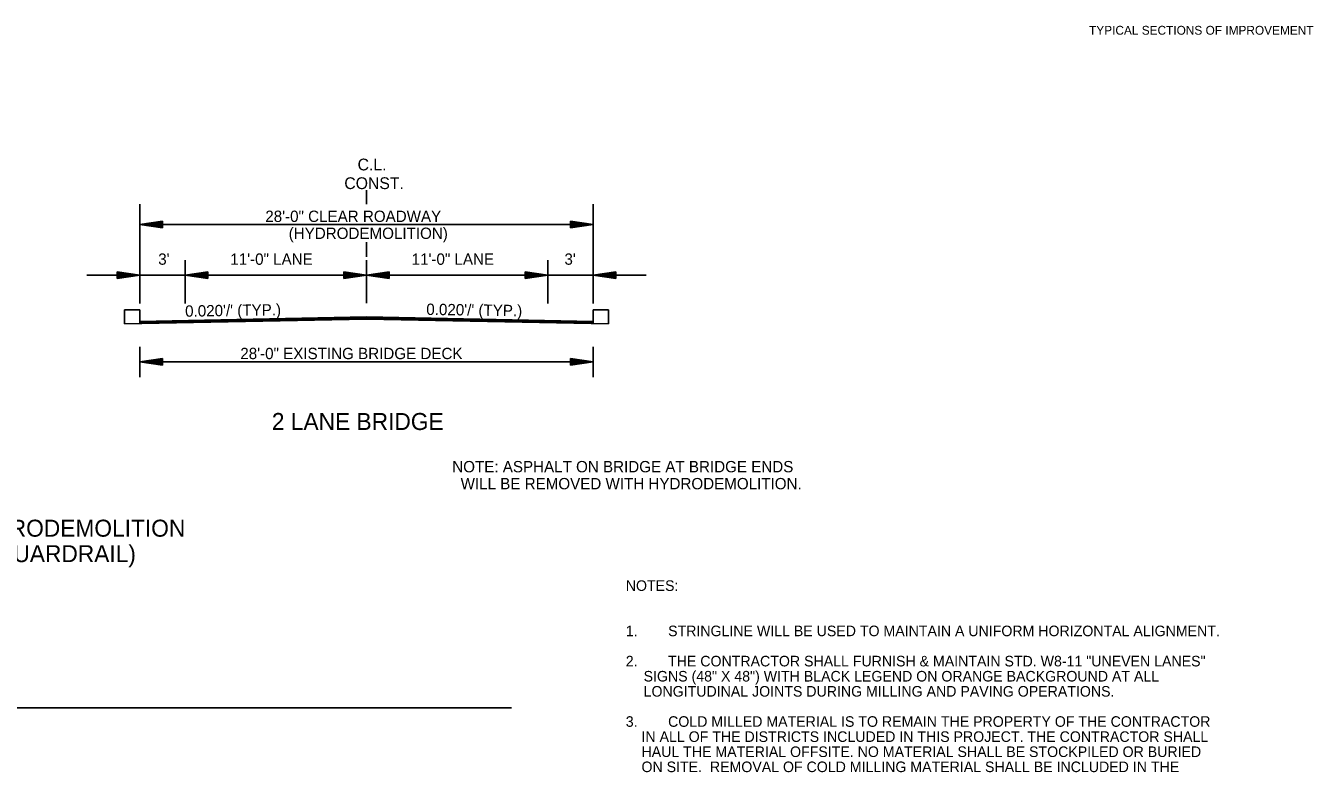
# Model space of a CAD drawing. Extents: x 544259 to 1930787, y -1961343 to 596640.
# Drawn here: x 544903 to 545755, y -1960851 to -1960356 of the extents above; entities that cross this region are included whole.
import ezdxf

# ---------------------------------------------------------------- set-up
doc = ezdxf.new("R2010")
doc.units = 0
for name, color, linetype in [('R_Border', 7, 'Continuous'), ('R_Border Notes', 7, 'Continuous'), ('R_Border Prem', 7, 'Continuous'), ('R_Draft', 7, 'Continuous')]:
    doc.layers.add(name, color=color, linetype=linetype)

msp = doc.modelspace()

# ---------------------------------------------------------------- linework, layer by layer
at = {"layer": 'R_Border'}
for p, q in [((544968.48, -1960544.64), (544968.47, -1960553.85)), ((544978.65, -1960544.64), (544968.48, -1960544.64)), ((544978.65, -1960553.38), (544978.65, -1960544.64)), ((545278.65, -1960553.38), (545278.65, -1960544.64)), ((545278.65, -1960544.64), (545288.82, -1960544.64)), ((545288.82, -1960544.64), (545288.83, -1960553.85)), ((544303.14, -1960808.08), (545224.71, -1960808.08))]:
    msp.add_line(p, q, dxfattribs=at)
at = {"layer": 'R_Draft'}
for p, q in [((545128.65, -1960474.62), (545128.65, -1960465.31)), ((544978.65, -1960540.4), (544978.65, -1960474.66)), ((545278.65, -1960540.4), (545278.65, -1960474.66)), ((544993.65, -1960485.78), (544978.65, -1960488.03)), ((544993.65, -1960490.28), (544978.65, -1960488.03)), ((544993.65, -1960486.16), (544981.15, -1960488.03)), ((544993.65, -1960489.91), (544981.15, -1960488.03)), ((544993.65, -1960486.54), (544983.73, -1960488.03)), ((544993.65, -1960489.53), (544983.73, -1960488.03)), ((544993.65, -1960486.92), (544986.23, -1960488.03)), ((544993.65, -1960489.15), (544986.23, -1960488.03)), ((544993.65, -1960487.3), (544988.77, -1960488.03)), ((544993.65, -1960488.76), (544988.77, -1960488.03)), ((544990.65, -1960488.03), (545266.65, -1960488.03)), ((544993.65, -1960487.68), (544991.28, -1960488.03)), ((544993.65, -1960488.39), (544991.28, -1960488.03)), ((544993.65, -1960490.28), (544993.65, -1960485.78)), ((545263.65, -1960485.78), (545278.65, -1960488.03)), ((545263.65, -1960485.78), (545263.65, -1960490.28)), ((545263.65, -1960486.16), (545276.14, -1960488.03)), ((545263.65, -1960486.54), (545273.56, -1960488.03)), ((545263.65, -1960486.92), (545271.07, -1960488.03)), ((545263.65, -1960487.31), (545268.52, -1960488.03)), ((545263.65, -1960487.68), (545266.02, -1960488.03)), ((545263.65, -1960490.28), (545278.65, -1960488.03)), ((545263.65, -1960488.77), (545268.52, -1960488.03)), ((545263.65, -1960489.53), (545273.56, -1960488.03)), ((545263.65, -1960489.91), (545276.14, -1960488.03)), ((545263.65, -1960489.15), (545271.07, -1960488.03)), ((545263.65, -1960488.39), (545266.02, -1960488.03)), ((545128.65, -1960509.55), (545128.65, -1960499.68)), ((545008.65, -1960540.4), (545008.65, -1960511.68)), ((545128.65, -1960540.23), (545128.65, -1960511.68)), ((545248.65, -1960540.4), (545248.65, -1960511.68)), ((545008.65, -1960521.57), (544943.65, -1960521.57)), ((544963.65, -1960519.32), (544978.65, -1960521.57)), ((544963.65, -1960519.32), (544963.65, -1960523.82)), ((544963.65, -1960519.7), (544976.14, -1960521.57)), ((544963.65, -1960520.08), (544973.56, -1960521.57)), ((544963.65, -1960520.45), (544971.07, -1960521.57)), ((544963.65, -1960520.84), (544968.52, -1960521.57)), ((544963.65, -1960521.22), (544966.02, -1960521.57)), ((544963.65, -1960523.82), (544978.65, -1960521.57)), ((544963.65, -1960522.31), (544968.52, -1960521.57)), ((544963.65, -1960523.06), (544973.56, -1960521.57)), ((544963.65, -1960523.45), (544976.14, -1960521.57)), ((544963.65, -1960522.69), (544971.07, -1960521.57)), ((544963.65, -1960521.92), (544966.02, -1960521.57)), ((545023.65, -1960519.32), (545008.65, -1960521.57)), ((545023.65, -1960523.82), (545008.65, -1960521.57)), ((545008.65, -1960521.57), (545128.65, -1960521.57)), ((545023.65, -1960519.7), (545011.15, -1960521.57)), ((545023.65, -1960523.45), (545011.15, -1960521.57)), ((545023.65, -1960520.08), (545013.73, -1960521.57)), ((545023.65, -1960523.06), (545013.73, -1960521.57)), ((545023.65, -1960520.45), (545016.23, -1960521.57)), ((545023.65, -1960522.69), (545016.23, -1960521.57)), ((545023.65, -1960520.84), (545018.77, -1960521.57)), ((545023.65, -1960522.3), (545018.77, -1960521.57)), ((545023.65, -1960521.22), (545021.28, -1960521.57)), ((545023.65, -1960521.92), (545021.28, -1960521.57)), ((545023.65, -1960523.82), (545023.65, -1960519.32)), ((545113.65, -1960519.32), (545128.65, -1960521.57)), ((545113.65, -1960519.32), (545113.65, -1960523.82)), ((545113.65, -1960519.7), (545126.14, -1960521.57)), ((545113.65, -1960520.08), (545123.56, -1960521.57)), ((545113.65, -1960520.45), (545121.07, -1960521.57)), ((545113.65, -1960520.84), (545118.52, -1960521.57)), ((545113.65, -1960521.22), (545116.02, -1960521.57)), ((545113.65, -1960523.82), (545128.65, -1960521.57)), ((545113.65, -1960522.31), (545118.52, -1960521.57)), ((545113.65, -1960523.06), (545123.56, -1960521.57)), ((545113.65, -1960523.45), (545126.14, -1960521.57)), ((545113.65, -1960522.69), (545121.07, -1960521.57)), ((545113.65, -1960521.92), (545116.02, -1960521.57)), ((545143.65, -1960519.32), (545128.65, -1960521.57)), ((545248.65, -1960521.57), (545128.65, -1960521.57)), ((545143.65, -1960523.82), (545128.65, -1960521.57)), ((545143.65, -1960519.7), (545131.15, -1960521.57)), ((545143.65, -1960523.45), (545131.15, -1960521.57)), ((545143.65, -1960520.08), (545133.73, -1960521.57)), ((545143.65, -1960523.06), (545133.73, -1960521.57)), ((545143.65, -1960520.45), (545136.23, -1960521.57)), ((545143.65, -1960522.69), (545136.23, -1960521.57)), ((545143.65, -1960520.84), (545138.77, -1960521.57)), ((545143.65, -1960522.31), (545138.77, -1960521.57)), ((545143.65, -1960521.22), (545141.28, -1960521.57)), ((545143.65, -1960521.92), (545141.28, -1960521.57)), ((545143.65, -1960519.32), (545143.65, -1960523.82)), ((545233.65, -1960519.32), (545248.65, -1960521.57)), ((545233.65, -1960523.82), (545233.65, -1960519.32)), ((545233.65, -1960519.7), (545246.14, -1960521.57)), ((545233.65, -1960520.08), (545243.56, -1960521.57)), ((545233.65, -1960520.45), (545241.07, -1960521.57)), ((545233.65, -1960520.84), (545238.52, -1960521.57)), ((545233.65, -1960521.22), (545236.02, -1960521.57)), ((545233.65, -1960523.82), (545248.65, -1960521.57)), ((545233.65, -1960522.3), (545238.52, -1960521.57)), ((545233.65, -1960523.06), (545243.56, -1960521.57)), ((545233.65, -1960523.45), (545246.14, -1960521.57)), ((545233.65, -1960522.69), (545241.07, -1960521.57)), ((545233.65, -1960521.92), (545236.02, -1960521.57)), ((545248.65, -1960521.57), (545278.65, -1960521.57)), ((545293.65, -1960519.32), (545278.65, -1960521.57)), ((545278.65, -1960521.57), (545313.65, -1960521.57)), ((545293.65, -1960523.82), (545278.65, -1960521.57)), ((545293.65, -1960519.7), (545281.15, -1960521.57)), ((545293.65, -1960523.45), (545281.15, -1960521.57)), ((545293.65, -1960520.08), (545283.73, -1960521.57)), ((545293.65, -1960523.06), (545283.73, -1960521.57)), ((545293.65, -1960520.45), (545286.23, -1960521.57)), ((545293.65, -1960522.69), (545286.23, -1960521.57)), ((545293.65, -1960520.84), (545288.77, -1960521.57)), ((545293.65, -1960522.31), (545288.77, -1960521.57)), ((545293.65, -1960521.22), (545291.28, -1960521.57)), ((545293.65, -1960521.92), (545291.28, -1960521.57)), ((545293.65, -1960519.32), (545293.65, -1960523.82)), ((545128.68, -1960550.68), (544968.47, -1960553.88)), ((545128.65, -1960549.18), (544978.65, -1960552.18)), ((545128.66, -1960549.48), (544978.65, -1960552.48)), ((545128.66, -1960549.78), (544978.65, -1960552.78)), ((545128.67, -1960550.08), (544978.65, -1960553.08)), ((545128.67, -1960550.38), (544978.65, -1960553.38)), ((545128.62, -1960550.68), (545288.83, -1960553.88)), ((545128.63, -1960550.08), (545278.65, -1960553.08)), ((545128.63, -1960550.38), (545278.65, -1960553.38)), ((545128.64, -1960549.48), (545278.65, -1960552.48)), ((545128.64, -1960549.78), (545278.65, -1960552.78)), ((545128.65, -1960549.18), (545278.65, -1960552.18)), ((544978.65, -1960569.04), (544978.65, -1960589.04)), ((545278.65, -1960569.04), (545278.65, -1960589.04)), ((544993.65, -1960576.79), (544978.65, -1960579.04)), ((544993.65, -1960577.16), (544981.15, -1960579.04)), ((544993.65, -1960577.54), (544983.73, -1960579.04)), ((544993.65, -1960577.92), (544986.23, -1960579.04)), ((544993.65, -1960581.29), (544993.65, -1960576.79)), ((545263.65, -1960576.79), (545278.65, -1960579.04)), ((545263.65, -1960576.79), (545263.65, -1960581.29)), ((545263.65, -1960577.16), (545276.14, -1960579.04)), ((545263.65, -1960577.54), (545273.56, -1960579.04)), ((545263.65, -1960577.92), (545271.07, -1960579.04)), ((544993.65, -1960581.29), (544978.65, -1960579.04)), ((544993.65, -1960580.91), (544981.15, -1960579.04)), ((544993.65, -1960580.53), (544983.73, -1960579.04)), ((544993.65, -1960580.15), (544986.23, -1960579.04)), ((544993.65, -1960578.3), (544988.77, -1960579.04)), ((544993.65, -1960579.76), (544988.77, -1960579.04)), ((544990.65, -1960579.04), (545268.65, -1960579.04)), ((544993.65, -1960578.68), (544991.28, -1960579.04)), ((544993.65, -1960579.39), (544991.28, -1960579.04)), ((545263.65, -1960578.31), (545268.52, -1960579.04)), ((545263.65, -1960578.68), (545266.02, -1960579.04)), ((545263.65, -1960581.29), (545278.65, -1960579.04)), ((545263.65, -1960579.77), (545268.52, -1960579.04)), ((545263.65, -1960580.53), (545273.56, -1960579.04)), ((545263.65, -1960580.91), (545276.14, -1960579.04)), ((545263.65, -1960580.15), (545271.07, -1960579.04)), ((545263.65, -1960579.39), (545266.02, -1960579.04))]:
    msp.add_line(p, q, dxfattribs=at)

# ---------------------------------------------------------------- texts
at = {"layer": 'R_Border Notes'}
for s, p in [('NOTES: ', (545300.26, -1960730.66)), ('1.', (545300.26, -1960760.66)), ('STRINGLINE WILL BE USED TO MAINTAIN A UNIFORM HORIZONTAL ALIGNMENT.', (545328.26, -1960760.66)), ('2.', (545300.26, -1960780.66)), ('THE CONTRACTOR SHALL FURNISH & MAINTAIN STD. W8-11 "UNEVEN LANES" ', (545328.26, -1960780.66)), ('    SIGNS (48" X 48") WITH BLACK LEGEND ON ORANGE BACKGROUND AT ALL ', (545301.66, -1960790.66)), ('    LONGITUDINAL JOINTS DURING MILLING AND PAVING OPERATIONS.', (545301.66, -1960800.66)), ('3.', (545300.26, -1960820.66)), ('COLD MILLED MATERIAL IS TO REMAIN THE PROPERTY OF THE CONTRACTOR', (545328.26, -1960820.66)), ('    IN ALL OF THE DISTRICTS INCLUDED IN THIS PROJECT. THE CONTRACTOR SHALL', (545300.26, -1960830.66)), ('    HAUL THE MATERIAL OFFSITE. NO MATERIAL SHALL BE STOCKPILED OR BURIED', (545300.26, -1960840.66)), ('    ON SITE.  REMOVAL OF COLD MILLING MATERIAL SHALL BE INCLUDED IN THE', (545300.26, -1960850.66))]:
    msp.add_text(s, height=7, dxfattribs=at).set_placement(p)
at = {"layer": 'R_Border Prem'}
msp.add_text('TYPICAL SECTIONS OF IMPROVEMENT', height=5.862, rotation=360, dxfattribs=at).set_placement((545606.81, -1960362.37))
at = {"layer": 'R_Draft'}
for s, height, p in [('C.L.', 7.8, (545122.8, -1960452.22)), ('CONST.', 7.8, (545114.02, -1960464.59)), ('28\'-0" CLEAR ROADWAY ', 7.5, (545061.74, -1960486.36)), ('(HYDRODEMOLITION)', 7.5, (545077.21, -1960497.61)), ("3'", 7.5, (544990.88, -1960514.71)), ('11\'-0" LANE', 7.5, (545038.59, -1960514.71)), ('11\'-0" LANE', 7.5, (545158.59, -1960514.71)), ("3'", 7.5, (545259.69, -1960514.71)), ('28\'-0" EXISTING BRIDGE DECK', 7.5, (545045.2, -1960577.2)), ('2 LANE BRIDGE', 11.25, (545066.06, -1960624.11)), ('NOTE: ASPHALT ON BRIDGE AT BRIDGE ENDS', 7.5, (545185.44, -1960652.14)), ('WILL BE REMOVED WITH HYDRODEMOLITION.', 7.5, (545190.99, -1960663.39)), ('28 FT. CLEAR ROADWAY BRIDGE - HYDRODEMOLITION', 11.25, (544605.91, -1960694.76)), ('(ROAD TRANSITIONS AND NEW GUARDRAIL)', 11.25, (544650.16, -1960711.63))]:
    msp.add_text(s, height=height, dxfattribs=at).set_placement(p)
for rotation, p in [(0.87191, (545008.74, -1960549.13)), (359.12809, (545168.22, -1960547.9))]:
    msp.add_text("0.020'/' (TYP.)", height=7.5, rotation=rotation, dxfattribs=at).set_placement(p)

doc.saveas('drawing.dxf')
